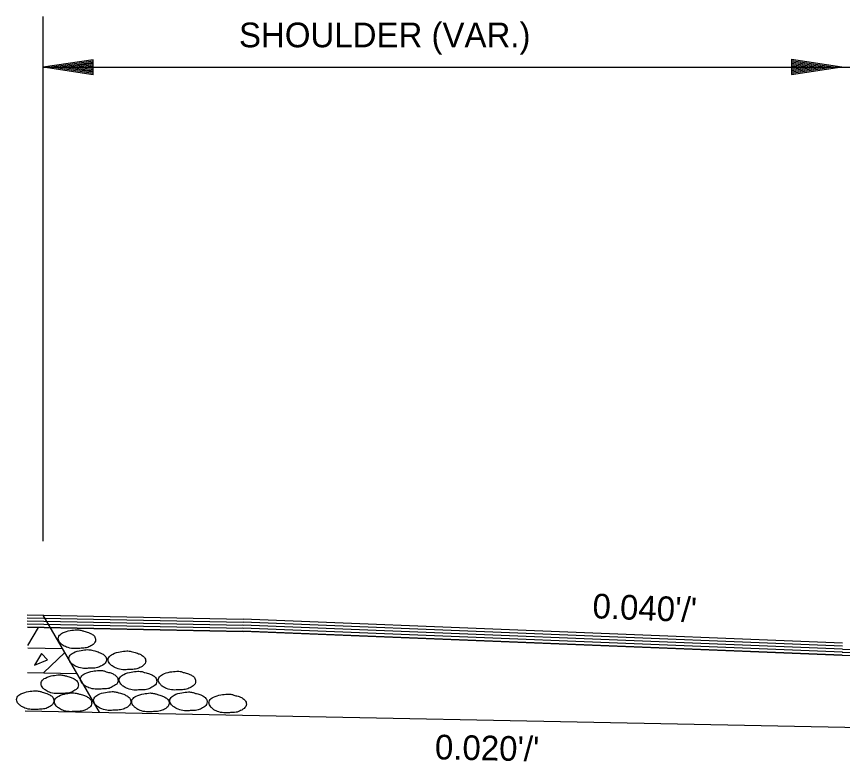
# Model space of a CAD drawing. Extents: x 1929624 to 1935547, y 596315 to 605721.
# Drawn here: x 1932824.7 to 1933028.1, y 604776.6 to 604960 of the extents above; entities that cross this region are included whole.
import ezdxf

# ---------------------------------------------------------------- set-up
doc = ezdxf.new("R2010")
doc.units = 0
doc.layers.add('Default', color=7, linetype='Continuous')

msp = doc.modelspace()

# ---------------------------------------------------------------- linework, layer by layer
at = {"layer": 'Default'}
for p, q in [((1932831.31, 604830.82), (1932831.31, 604959.96)), ((1932843.64, 604949.31), (1932831.31, 604947.46)), ((1932843.64, 604945.59), (1932843.64, 604949.31)), ((1933015.57, 604949.43), (1933027.9, 604947.56)), ((1933015.57, 604949.43), (1933015.57, 604945.71)), ((1932831.31, 604947.46), (1933161.84, 604947.46)), ((1932843.64, 604945.59), (1932831.31, 604947.46)), ((1932843.64, 604948.99), (1932833.38, 604947.46)), ((1932843.64, 604945.91), (1932833.38, 604947.46)), ((1932843.64, 604948.67), (1932835.5, 604947.46)), ((1932843.64, 604946.23), (1932835.5, 604947.46)), ((1932843.64, 604948.37), (1932837.56, 604947.46)), ((1932843.64, 604946.53), (1932837.56, 604947.46)), ((1932843.64, 604948.05), (1932839.63, 604947.46)), ((1932843.64, 604946.85), (1932839.63, 604947.46)), ((1932843.64, 604947.73), (1932841.7, 604947.46)), ((1932843.64, 604947.17), (1932841.7, 604947.46)), ((1933015.57, 604949.11), (1933025.83, 604947.56)), ((1933015.57, 604948.79), (1933023.72, 604947.56)), ((1933015.57, 604948.49), (1933021.65, 604947.56)), ((1933015.57, 604948.18), (1933019.58, 604947.56)), ((1933015.57, 604947.86), (1933017.52, 604947.56)), ((1933015.57, 604945.71), (1933027.9, 604947.56)), ((1933015.57, 604946.97), (1933019.58, 604947.56)), ((1933015.57, 604946.35), (1933023.72, 604947.56)), ((1933015.57, 604946.03), (1933025.83, 604947.56)), ((1933015.57, 604946.65), (1933021.65, 604947.56)), ((1933015.57, 604947.29), (1933017.52, 604947.56)), ((1932827.35, 604812.66), (1932880.52, 604811.6)), ((1932827.35, 604811.92), (1932880.52, 604810.86)), ((1932827.38, 604811.18), (1932880.52, 604810.12)), ((1932845.14, 604788.67), (1932831.31, 604812.58)), ((1933028.14, 604805.69), (1932880.52, 604811.6)), ((1932827.4, 604810.44), (1932880.52, 604809.39)), ((1932827.43, 604809.71), (1932880.47, 604808.65)), ((1932827.43, 604809.61), (1932880.52, 604808.55)), ((1932827.53, 604805.13), (1932830.18, 604809.58)), ((1933028.1, 604804.22), (1932880.47, 604810.12)), ((1933028.1, 604803.48), (1932880.47, 604809.39)), ((1933028.14, 604804.96), (1932880.52, 604810.86)), ((1933028.05, 604802.74), (1932880.42, 604808.65)), ((1933028.05, 604802.64), (1932880.52, 604808.55)), ((1932827.55, 604804.54), (1932836.06, 604804.37)), ((1932831.41, 604798.41), (1932836.65, 604803.36)), ((1933028.05, 604803.48), (1933162.7, 604798.09)), ((1933028.08, 604804.22), (1933162.73, 604798.83)), ((1933028.02, 604802.74), (1933162.68, 604797.35)), ((1932827.43, 604798.49), (1932839.6, 604798.25)), ((1932826.87, 604789.04), (1933220.25, 604781.21))]:
    msp.add_line(p, q, dxfattribs=at)
msp.add_lwpolyline([(1932829.16, 604800.27), (1932832.41, 604801.6), (1932830.93, 604803.18), (1932829.16, 604800.27)], dxfattribs=at)
for points in [[(1932839.59, 604809.01), (1932837.97, 604808.81), (1932836.1, 604808.22), (1932835.16, 604807.38), (1932835.01, 604806.79), (1932835.46, 604805.81), (1932836, 604805.32), (1932837.08, 604804.73), (1932838.65, 604804.38), (1932839.44, 604804.38), (1932840.67, 604804.43), (1932842, 604804.58), (1932843.08, 604805.02), (1932844.07, 604805.91), (1932844.21, 604806.5), (1932843.92, 604807.38), (1932843.18, 604807.97), (1932842.44, 604808.32), (1932841.36, 604808.66), (1932840.62, 604808.86), (1932839.59, 604809.01)], [(1932842.26, 604804.12), (1932840.64, 604803.92), (1932838.77, 604803.33), (1932837.79, 604802.5), (1932837.64, 604801.91), (1932838.08, 604800.92), (1932838.62, 604800.43), (1932839.7, 604799.84), (1932841.28, 604799.49), (1932842.12, 604799.49), (1932843.35, 604799.54), (1932844.67, 604799.69), (1932845.71, 604800.13), (1932846.74, 604801.02), (1932846.89, 604801.61), (1932846.59, 604802.5), (1932845.86, 604803.09), (1932845.12, 604803.43), (1932843.99, 604803.78), (1932843.3, 604803.97), (1932842.26, 604804.12)], [(1932851.92, 604803.8), (1932850.3, 604803.6), (1932848.43, 604803.01), (1932847.45, 604802.18), (1932847.3, 604801.59), (1932847.74, 604800.6), (1932848.28, 604800.11), (1932849.37, 604799.52), (1932850.94, 604799.17), (1932851.78, 604799.17), (1932853.01, 604799.22), (1932854.34, 604799.37), (1932855.37, 604799.81), (1932856.4, 604800.7), (1932856.55, 604801.29), (1932856.25, 604802.18), (1932855.52, 604802.77), (1932854.78, 604803.11), (1932853.65, 604803.46), (1932852.96, 604803.65), (1932851.92, 604803.8)], [(1932845.13, 604799), (1932843.5, 604798.81), (1932841.63, 604798.22), (1932840.65, 604797.38), (1932840.5, 604796.84), (1932840.94, 604795.85), (1932841.48, 604795.31), (1932842.57, 604794.72), (1932844.14, 604794.38), (1932844.98, 604794.38), (1932846.21, 604794.43), (1932847.54, 604794.57), (1932848.57, 604795.07), (1932849.6, 604795.9), (1932849.75, 604796.54), (1932849.46, 604797.43), (1932848.72, 604798.02), (1932847.98, 604798.36), (1932846.85, 604798.66), (1932846.16, 604798.9), (1932845.13, 604799)], [(1932854.64, 604798.78), (1932853.01, 604798.58), (1932851.14, 604797.99), (1932850.16, 604797.16), (1932850.01, 604796.62), (1932850.46, 604795.63), (1932851, 604795.09), (1932852.08, 604794.5), (1932853.65, 604794.16), (1932854.49, 604794.16), (1932855.72, 604794.2), (1932857.05, 604794.35), (1932858.08, 604794.84), (1932859.12, 604795.68), (1932859.26, 604796.32), (1932858.97, 604797.21), (1932858.23, 604797.8), (1932857.49, 604798.14), (1932856.36, 604798.44), (1932855.67, 604798.68), (1932854.64, 604798.78)], [(1932864.22, 604798.8), (1932862.59, 604798.6), (1932860.72, 604798.01), (1932859.79, 604797.17), (1932859.64, 604796.63), (1932860.08, 604795.65), (1932860.63, 604795.11), (1932861.71, 604794.52), (1932863.28, 604794.17), (1932864.07, 604794.17), (1932865.3, 604794.22), (1932866.63, 604794.37), (1932867.71, 604794.86), (1932868.7, 604795.7), (1932868.84, 604796.34), (1932868.55, 604797.22), (1932867.81, 604797.81), (1932867.07, 604798.16), (1932865.99, 604798.45), (1932865.25, 604798.7), (1932864.22, 604798.8)], [(1932835.36, 604797.91), (1932833.73, 604797.71), (1932831.86, 604797.12), (1932830.93, 604796.29), (1932830.78, 604795.7), (1932831.22, 604794.71), (1932831.77, 604794.22), (1932832.85, 604793.63), (1932834.42, 604793.29), (1932835.21, 604793.29), (1932836.44, 604793.34), (1932837.77, 604793.48), (1932838.85, 604793.93), (1932839.84, 604794.81), (1932839.98, 604795.4), (1932839.69, 604796.29), (1932838.95, 604796.88), (1932838.21, 604797.22), (1932837.13, 604797.57), (1932836.39, 604797.76), (1932835.36, 604797.91)], [(1932829.33, 604794), (1932827.71, 604793.8), (1932825.84, 604793.21), (1932824.9, 604792.38), (1932824.75, 604791.79), (1932825.2, 604790.8), (1932825.74, 604790.31), (1932826.82, 604789.72), (1932828.39, 604789.37), (1932829.18, 604789.37), (1932830.41, 604789.42), (1932831.74, 604789.57), (1932832.82, 604790.01), (1932833.81, 604790.9), (1932833.96, 604791.49), (1932833.66, 604792.38), (1932832.92, 604792.97), (1932832.18, 604793.31), (1932831.1, 604793.66), (1932830.36, 604793.85), (1932829.33, 604794)], [(1932838.64, 604793.47), (1932837.01, 604793.27), (1932835.14, 604792.68), (1932834.21, 604791.84), (1932834.06, 604791.25), (1932834.5, 604790.27), (1932835.05, 604789.78), (1932836.13, 604789.19), (1932837.7, 604788.84), (1932838.49, 604788.84), (1932839.72, 604788.89), (1932841.05, 604789.04), (1932842.13, 604789.48), (1932843.12, 604790.37), (1932843.26, 604790.96), (1932842.97, 604791.84), (1932842.23, 604792.43), (1932841.49, 604792.78), (1932840.41, 604793.12), (1932839.67, 604793.32), (1932838.64, 604793.47)], [(1932848.28, 604793.79), (1932846.66, 604793.59), (1932844.79, 604793), (1932843.85, 604792.16), (1932843.71, 604791.57), (1932844.15, 604790.59), (1932844.69, 604790.1), (1932845.77, 604789.51), (1932847.35, 604789.16), (1932848.14, 604789.16), (1932849.37, 604789.21), (1932850.69, 604789.36), (1932851.78, 604789.8), (1932852.76, 604790.69), (1932852.91, 604791.28), (1932852.61, 604792.16), (1932851.87, 604792.75), (1932851.14, 604793.1), (1932850.05, 604793.44), (1932849.32, 604793.64), (1932848.28, 604793.79)], [(1932857.68, 604793.43), (1932856.06, 604793.23), (1932854.19, 604792.64), (1932853.25, 604791.8), (1932853.1, 604791.21), (1932853.55, 604790.23), (1932854.09, 604789.74), (1932855.17, 604789.14), (1932856.75, 604788.8), (1932857.53, 604788.8), (1932858.76, 604788.85), (1932860.09, 604789), (1932861.18, 604789.44), (1932862.16, 604790.33), (1932862.31, 604790.92), (1932862.01, 604791.8), (1932861.27, 604792.39), (1932860.54, 604792.74), (1932859.45, 604793.08), (1932858.71, 604793.28), (1932857.68, 604793.43)], [(1932867.06, 604793.69), (1932865.43, 604793.49), (1932863.56, 604792.9), (1932862.63, 604792.06), (1932862.48, 604791.52), (1932862.92, 604790.54), (1932863.46, 604790), (1932864.55, 604789.41), (1932866.12, 604789.06), (1932866.91, 604789.06), (1932868.14, 604789.11), (1932869.47, 604789.26), (1932870.55, 604789.75), (1932871.53, 604790.59), (1932871.68, 604791.23), (1932871.39, 604792.11), (1932870.65, 604792.7), (1932869.91, 604793.05), (1932868.83, 604793.34), (1932868.09, 604793.59), (1932867.06, 604793.69)], [(1932876.7, 604793.18), (1932875.08, 604792.98), (1932873.21, 604792.39), (1932872.27, 604791.56), (1932872.12, 604791.01), (1932872.57, 604790.03), (1932873.11, 604789.49), (1932874.19, 604788.9), (1932875.77, 604788.55), (1932876.55, 604788.55), (1932877.78, 604788.6), (1932879.11, 604788.75), (1932880.19, 604789.24), (1932881.18, 604790.08), (1932881.33, 604790.72), (1932881.03, 604791.6), (1932880.29, 604792.2), (1932879.55, 604792.54), (1932878.47, 604792.84), (1932877.73, 604793.08), (1932876.7, 604793.18)]]:
    msp.add_spline(points, degree=3, dxfattribs=at)

# ---------------------------------------------------------------- texts
for s, rotation, p in [('SHOULDER (VAR.)', 360, (1932879.52, 604952.39)), ("0.040'/'", 357.7094, (1932966.46, 604811.85)), ("0.020'/'", 358.8537, (1932927.71, 604777.11))]:
    msp.add_text(s, height=6.075, rotation=rotation, dxfattribs=at).set_placement(p)

doc.saveas('drawing.dxf')
